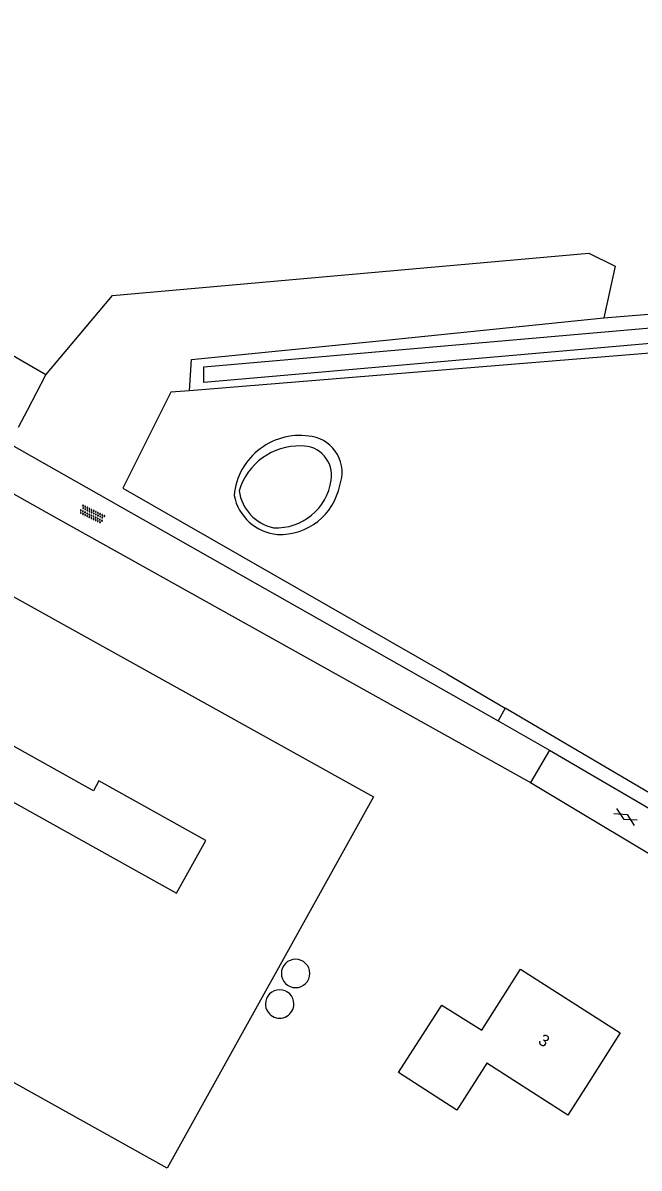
# Model space of a CAD drawing. Extents: x 133000 to 136000, y 400500 to 403500.
# Drawn here: x 134687.1 to 134739.2, y 402087.9 to 402184.6 of the extents above; entities that cross this region are included whole.
import ezdxf

# ---------------------------------------------------------------- set-up
doc = ezdxf.new("R2010")
doc.units = 0
for name, color, linetype in [('gg-afsc-draadraster', 7, 'Continuous'), ('gg-afsc-lijn draadraster', 7, 'Continuous'), ('gg-anno-huisnummerreeks BGT', 7, 'Continuous'), ('gg-bbg-bijgebouw', 7, 'Continuous'), ('gg-bbg-hoofdgebouw', 7, 'Continuous'), ('gg-bbg-opslagtank', 7, 'Continuous'), ('gg-knt-bronhoudergrens', 7, 'Continuous'), ('gg-knt-onverhard', 7, 'Continuous'), ('gg-knt-verharding', 7, 'Continuous'), ('gg-kntw-bovenkant insteek waterloop', 7, 'Continuous'), ('gg-kntw-waterlijn', 7, 'Continuous'), ('gt-grn-groengrens', 7, 'Continuous'), ('gt-symb-gesloten verharding', 7, 'Continuous'), ('gt-symb-overige verharding', 7, 'Continuous')]:
    doc.layers.add(name, color=color, linetype=linetype)

# ---------------------------------------------------------------- blocks, each defined once
blk = doc.blocks.new('gt0-GESVH1')
at = {"layer": 'gt-symb-gesloten verharding'}
for p, q in [((-0.992, -0.261), (0.008, 0.239)), ((0.008, -0.261), (-0.992, 0.239)), ((0.008, 0.239), (1.008, -0.261)), ((1.008, 0.239), (0.008, -0.261))]:
    blk.add_line(p, q, dxfattribs=at)
blk = doc.blocks.new('gt0-OVH')
at = {"layer": 'gt-symb-overige verharding'}
for points in [[(-0.972, 0.298), (-0.967, 0.308), (-0.965, 0.319), (-0.966, 0.33), (-0.971, 0.34), (-0.978, 0.348), (-0.988, 0.353), (-0.999, 0.355), (-1.01, 0.354), (-1.02, 0.349), (-1.028, 0.342), (-1.033, 0.332), (-1.035, 0.321), (-1.034, 0.31), (-1.029, 0.3), (-1.022, 0.292), (-1.012, 0.287), (-1.001, 0.285), (-0.99, 0.286), (-0.98, 0.291)], [(-0.872, 0.106), (-0.867, 0.116), (-0.865, 0.126), (-0.866, 0.137), (-0.871, 0.147), (-0.878, 0.156), (-0.888, 0.161), (-0.899, 0.163), (-0.91, 0.162), (-0.92, 0.157), (-0.928, 0.15), (-0.933, 0.14), (-0.935, 0.129), (-0.934, 0.118), (-0.929, 0.108), (-0.922, 0.1), (-0.912, 0.095), (-0.901, 0.092), (-0.89, 0.094), (-0.88, 0.098)], [(-0.772, 0.298), (-0.767, 0.308), (-0.765, 0.319), (-0.766, 0.33), (-0.771, 0.34), (-0.778, 0.348), (-0.788, 0.353), (-0.799, 0.355), (-0.81, 0.354), (-0.82, 0.349), (-0.828, 0.342), (-0.833, 0.332), (-0.835, 0.321), (-0.834, 0.31), (-0.829, 0.3), (-0.822, 0.292), (-0.812, 0.287), (-0.801, 0.285), (-0.79, 0.286), (-0.78, 0.291)], [(-0.672, 0.106), (-0.667, 0.116), (-0.665, 0.126), (-0.666, 0.137), (-0.671, 0.147), (-0.678, 0.156), (-0.688, 0.161), (-0.699, 0.163), (-0.71, 0.162), (-0.72, 0.157), (-0.728, 0.15), (-0.733, 0.14), (-0.735, 0.129), (-0.734, 0.118), (-0.729, 0.108), (-0.722, 0.1), (-0.712, 0.095), (-0.701, 0.092), (-0.69, 0.094), (-0.68, 0.098)], [(-0.572, 0.298), (-0.567, 0.308), (-0.565, 0.319), (-0.566, 0.33), (-0.571, 0.34), (-0.578, 0.348), (-0.588, 0.353), (-0.599, 0.355), (-0.61, 0.354), (-0.62, 0.349), (-0.628, 0.342), (-0.633, 0.332), (-0.635, 0.321), (-0.634, 0.31), (-0.629, 0.3), (-0.622, 0.292), (-0.612, 0.287), (-0.601, 0.285), (-0.59, 0.286), (-0.58, 0.291)], [(-0.472, 0.106), (-0.467, 0.116), (-0.465, 0.126), (-0.466, 0.137), (-0.471, 0.147), (-0.478, 0.156), (-0.488, 0.161), (-0.499, 0.163), (-0.51, 0.162), (-0.52, 0.157), (-0.528, 0.15), (-0.533, 0.14), (-0.535, 0.129), (-0.534, 0.118), (-0.529, 0.108), (-0.522, 0.1), (-0.512, 0.095), (-0.501, 0.092), (-0.49, 0.094), (-0.48, 0.098)], [(-0.372, 0.298), (-0.367, 0.308), (-0.365, 0.319), (-0.366, 0.33), (-0.371, 0.34), (-0.378, 0.348), (-0.388, 0.353), (-0.399, 0.355), (-0.41, 0.354), (-0.42, 0.349), (-0.428, 0.342), (-0.433, 0.332), (-0.435, 0.321), (-0.434, 0.31), (-0.429, 0.3), (-0.422, 0.292), (-0.412, 0.287), (-0.401, 0.285), (-0.39, 0.286), (-0.38, 0.291)], [(-0.272, 0.106), (-0.267, 0.116), (-0.265, 0.126), (-0.266, 0.137), (-0.271, 0.147), (-0.278, 0.156), (-0.288, 0.161), (-0.299, 0.163), (-0.31, 0.162), (-0.32, 0.157), (-0.328, 0.15), (-0.333, 0.14), (-0.335, 0.129), (-0.334, 0.118), (-0.329, 0.108), (-0.322, 0.1), (-0.312, 0.095), (-0.301, 0.092), (-0.29, 0.094), (-0.28, 0.098)], [(-0.172, 0.298), (-0.167, 0.308), (-0.165, 0.319), (-0.166, 0.33), (-0.171, 0.34), (-0.178, 0.348), (-0.188, 0.353), (-0.199, 0.355), (-0.21, 0.354), (-0.22, 0.349), (-0.228, 0.342), (-0.233, 0.332), (-0.235, 0.321), (-0.234, 0.31), (-0.229, 0.3), (-0.222, 0.292), (-0.212, 0.287), (-0.201, 0.285), (-0.19, 0.286), (-0.18, 0.291)], [(-0.072, 0.106), (-0.067, 0.116), (-0.065, 0.126), (-0.066, 0.137), (-0.071, 0.147), (-0.078, 0.156), (-0.088, 0.161), (-0.099, 0.163), (-0.11, 0.162), (-0.12, 0.157), (-0.128, 0.15), (-0.133, 0.14), (-0.135, 0.129), (-0.134, 0.118), (-0.129, 0.108), (-0.122, 0.1), (-0.112, 0.095), (-0.101, 0.092), (-0.09, 0.094), (-0.08, 0.098)], [(0.028, 0.298), (0.033, 0.308), (0.035, 0.319), (0.034, 0.33), (0.029, 0.34), (0.022, 0.348), (0.012, 0.353), (0.001, 0.355), (-0.01, 0.354), (-0.02, 0.349), (-0.028, 0.342), (-0.033, 0.332), (-0.035, 0.321), (-0.034, 0.31), (-0.029, 0.3), (-0.022, 0.292), (-0.012, 0.287), (-0.001, 0.285), (0.01, 0.286), (0.02, 0.291)], [(0.128, 0.106), (0.133, 0.116), (0.135, 0.126), (0.134, 0.137), (0.129, 0.147), (0.122, 0.156), (0.112, 0.161), (0.101, 0.163), (0.09, 0.162), (0.08, 0.157), (0.072, 0.15), (0.067, 0.14), (0.065, 0.129), (0.066, 0.118), (0.071, 0.108), (0.078, 0.1), (0.088, 0.095), (0.099, 0.092), (0.11, 0.094), (0.12, 0.098)], [(0.228, 0.298), (0.233, 0.308), (0.235, 0.319), (0.234, 0.33), (0.229, 0.34), (0.222, 0.348), (0.212, 0.353), (0.201, 0.355), (0.19, 0.354), (0.18, 0.349), (0.172, 0.342), (0.167, 0.332), (0.165, 0.321), (0.166, 0.31), (0.171, 0.3), (0.178, 0.292), (0.188, 0.287), (0.199, 0.285), (0.21, 0.286), (0.22, 0.291)], [(0.328, 0.106), (0.333, 0.116), (0.335, 0.126), (0.334, 0.137), (0.329, 0.147), (0.322, 0.156), (0.312, 0.161), (0.301, 0.163), (0.29, 0.162), (0.28, 0.157), (0.272, 0.15), (0.267, 0.14), (0.265, 0.129), (0.266, 0.118), (0.271, 0.108), (0.278, 0.1), (0.288, 0.095), (0.299, 0.092), (0.31, 0.094), (0.32, 0.098)], [(0.428, 0.298), (0.433, 0.308), (0.435, 0.319), (0.434, 0.33), (0.429, 0.34), (0.422, 0.348), (0.412, 0.353), (0.401, 0.355), (0.39, 0.354), (0.38, 0.349), (0.372, 0.342), (0.367, 0.332), (0.365, 0.321), (0.366, 0.31), (0.371, 0.3), (0.378, 0.292), (0.388, 0.287), (0.399, 0.285), (0.41, 0.286), (0.42, 0.291)], [(0.528, 0.106), (0.533, 0.116), (0.535, 0.126), (0.534, 0.137), (0.529, 0.147), (0.522, 0.156), (0.512, 0.161), (0.501, 0.163), (0.49, 0.162), (0.48, 0.157), (0.472, 0.15), (0.467, 0.14), (0.465, 0.129), (0.466, 0.118), (0.471, 0.108), (0.478, 0.1), (0.488, 0.095), (0.499, 0.092), (0.51, 0.094), (0.52, 0.098)], [(0.628, 0.298), (0.633, 0.308), (0.635, 0.319), (0.634, 0.33), (0.629, 0.34), (0.622, 0.348), (0.612, 0.353), (0.601, 0.355), (0.59, 0.354), (0.58, 0.349), (0.572, 0.342), (0.567, 0.332), (0.565, 0.321), (0.566, 0.31), (0.571, 0.3), (0.578, 0.292), (0.588, 0.287), (0.599, 0.285), (0.61, 0.286), (0.62, 0.291)], [(0.728, 0.106), (0.733, 0.116), (0.735, 0.126), (0.734, 0.137), (0.729, 0.147), (0.722, 0.156), (0.712, 0.161), (0.701, 0.163), (0.69, 0.162), (0.68, 0.157), (0.672, 0.15), (0.667, 0.14), (0.665, 0.129), (0.666, 0.118), (0.671, 0.108), (0.678, 0.1), (0.688, 0.095), (0.699, 0.092), (0.71, 0.094), (0.72, 0.098)], [(0.828, 0.298), (0.833, 0.308), (0.835, 0.319), (0.834, 0.33), (0.829, 0.34), (0.822, 0.348), (0.812, 0.353), (0.801, 0.355), (0.79, 0.354), (0.78, 0.349), (0.772, 0.342), (0.767, 0.332), (0.765, 0.321), (0.766, 0.31), (0.771, 0.3), (0.778, 0.292), (0.788, 0.287), (0.799, 0.285), (0.81, 0.286), (0.82, 0.291)], [(0.928, 0.106), (0.933, 0.116), (0.935, 0.126), (0.934, 0.137), (0.929, 0.147), (0.922, 0.156), (0.912, 0.161), (0.901, 0.163), (0.89, 0.162), (0.88, 0.157), (0.872, 0.15), (0.867, 0.14), (0.865, 0.129), (0.866, 0.118), (0.871, 0.108), (0.878, 0.1), (0.888, 0.095), (0.899, 0.092), (0.91, 0.094), (0.92, 0.098)], [(1.028, 0.298), (1.033, 0.308), (1.035, 0.319), (1.034, 0.33), (1.029, 0.34), (1.022, 0.348), (1.012, 0.353), (1.001, 0.355), (0.99, 0.354), (0.98, 0.349), (0.972, 0.342), (0.967, 0.332), (0.965, 0.321), (0.966, 0.31), (0.971, 0.3), (0.978, 0.292), (0.988, 0.287), (0.999, 0.285), (1.01, 0.286), (1.02, 0.291)], [(-0.972, -0.142), (-0.967, -0.132), (-0.965, -0.121), (-0.966, -0.11), (-0.971, -0.1), (-0.978, -0.092), (-0.988, -0.087), (-0.999, -0.085), (-1.01, -0.086), (-1.02, -0.091), (-1.028, -0.098), (-1.033, -0.108), (-1.035, -0.119), (-1.034, -0.13), (-1.029, -0.14), (-1.022, -0.148), (-1.012, -0.153), (-1.001, -0.155), (-0.99, -0.154), (-0.98, -0.149)], [(-0.872, -0.334), (-0.867, -0.324), (-0.865, -0.314), (-0.866, -0.303), (-0.871, -0.293), (-0.878, -0.284), (-0.888, -0.279), (-0.899, -0.277), (-0.91, -0.278), (-0.92, -0.283), (-0.928, -0.29), (-0.933, -0.3), (-0.935, -0.311), (-0.934, -0.322), (-0.929, -0.332), (-0.922, -0.34), (-0.912, -0.345), (-0.901, -0.348), (-0.89, -0.346), (-0.88, -0.342)], [(-0.772, -0.142), (-0.767, -0.132), (-0.765, -0.121), (-0.766, -0.11), (-0.771, -0.1), (-0.778, -0.092), (-0.788, -0.087), (-0.799, -0.085), (-0.81, -0.086), (-0.82, -0.091), (-0.828, -0.098), (-0.833, -0.108), (-0.835, -0.119), (-0.834, -0.13), (-0.829, -0.14), (-0.822, -0.148), (-0.812, -0.153), (-0.801, -0.155), (-0.79, -0.154), (-0.78, -0.149)], [(-0.672, -0.334), (-0.667, -0.324), (-0.665, -0.314), (-0.666, -0.303), (-0.671, -0.293), (-0.678, -0.284), (-0.688, -0.279), (-0.699, -0.277), (-0.71, -0.278), (-0.72, -0.283), (-0.728, -0.29), (-0.733, -0.3), (-0.735, -0.311), (-0.734, -0.322), (-0.729, -0.332), (-0.722, -0.34), (-0.712, -0.345), (-0.701, -0.348), (-0.69, -0.346), (-0.68, -0.342)], [(-0.572, -0.142), (-0.567, -0.132), (-0.565, -0.121), (-0.566, -0.11), (-0.571, -0.1), (-0.578, -0.092), (-0.588, -0.087), (-0.599, -0.085), (-0.61, -0.086), (-0.62, -0.091), (-0.628, -0.098), (-0.633, -0.108), (-0.635, -0.119), (-0.634, -0.13), (-0.629, -0.14), (-0.622, -0.148), (-0.612, -0.153), (-0.601, -0.155), (-0.59, -0.154), (-0.58, -0.149)], [(-0.472, -0.334), (-0.467, -0.324), (-0.465, -0.314), (-0.466, -0.303), (-0.471, -0.293), (-0.478, -0.284), (-0.488, -0.279), (-0.499, -0.277), (-0.51, -0.278), (-0.52, -0.283), (-0.528, -0.29), (-0.533, -0.3), (-0.535, -0.311), (-0.534, -0.322), (-0.529, -0.332), (-0.522, -0.34), (-0.512, -0.345), (-0.501, -0.348), (-0.49, -0.346), (-0.48, -0.342)], [(-0.372, -0.142), (-0.367, -0.132), (-0.365, -0.121), (-0.366, -0.11), (-0.371, -0.1), (-0.378, -0.092), (-0.388, -0.087), (-0.399, -0.085), (-0.41, -0.086), (-0.42, -0.091), (-0.428, -0.098), (-0.433, -0.108), (-0.435, -0.119), (-0.434, -0.13), (-0.429, -0.14), (-0.422, -0.148), (-0.412, -0.153), (-0.401, -0.155), (-0.39, -0.154), (-0.38, -0.149)], [(-0.272, -0.334), (-0.267, -0.324), (-0.265, -0.314), (-0.266, -0.303), (-0.271, -0.293), (-0.278, -0.284), (-0.288, -0.279), (-0.299, -0.277), (-0.31, -0.278), (-0.32, -0.283), (-0.328, -0.29), (-0.333, -0.3), (-0.335, -0.311), (-0.334, -0.322), (-0.329, -0.332), (-0.322, -0.34), (-0.312, -0.345), (-0.301, -0.348), (-0.29, -0.346), (-0.28, -0.342)], [(-0.172, -0.142), (-0.167, -0.132), (-0.165, -0.121), (-0.166, -0.11), (-0.171, -0.1), (-0.178, -0.092), (-0.188, -0.087), (-0.199, -0.085), (-0.21, -0.086), (-0.22, -0.091), (-0.228, -0.098), (-0.233, -0.108), (-0.235, -0.119), (-0.234, -0.13), (-0.229, -0.14), (-0.222, -0.148), (-0.212, -0.153), (-0.201, -0.155), (-0.19, -0.154), (-0.18, -0.149)], [(-0.072, -0.334), (-0.067, -0.324), (-0.065, -0.314), (-0.066, -0.303), (-0.071, -0.293), (-0.078, -0.284), (-0.088, -0.279), (-0.099, -0.277), (-0.11, -0.278), (-0.12, -0.283), (-0.128, -0.29), (-0.133, -0.3), (-0.135, -0.311), (-0.134, -0.322), (-0.129, -0.332), (-0.122, -0.34), (-0.112, -0.345), (-0.101, -0.348), (-0.09, -0.346), (-0.08, -0.342)], [(0.028, -0.142), (0.033, -0.132), (0.035, -0.121), (0.034, -0.11), (0.029, -0.1), (0.022, -0.092), (0.012, -0.087), (0.001, -0.085), (-0.01, -0.086), (-0.02, -0.091), (-0.028, -0.098), (-0.033, -0.108), (-0.035, -0.119), (-0.034, -0.13), (-0.029, -0.14), (-0.022, -0.148), (-0.012, -0.153), (-0.001, -0.155), (0.01, -0.154), (0.02, -0.149)], [(0.128, -0.334), (0.133, -0.324), (0.135, -0.314), (0.134, -0.303), (0.129, -0.293), (0.122, -0.284), (0.112, -0.279), (0.101, -0.277), (0.09, -0.278), (0.08, -0.283), (0.072, -0.29), (0.067, -0.3), (0.065, -0.311), (0.066, -0.322), (0.071, -0.332), (0.078, -0.34), (0.088, -0.345), (0.099, -0.348), (0.11, -0.346), (0.12, -0.342)], [(0.228, -0.142), (0.233, -0.132), (0.235, -0.121), (0.234, -0.11), (0.229, -0.1), (0.222, -0.092), (0.212, -0.087), (0.201, -0.085), (0.19, -0.086), (0.18, -0.091), (0.172, -0.098), (0.167, -0.108), (0.165, -0.119), (0.166, -0.13), (0.171, -0.14), (0.178, -0.148), (0.188, -0.153), (0.199, -0.155), (0.21, -0.154), (0.22, -0.149)], [(0.328, -0.334), (0.333, -0.324), (0.335, -0.314), (0.334, -0.303), (0.329, -0.293), (0.322, -0.284), (0.312, -0.279), (0.301, -0.277), (0.29, -0.278), (0.28, -0.283), (0.272, -0.29), (0.267, -0.3), (0.265, -0.311), (0.266, -0.322), (0.271, -0.332), (0.278, -0.34), (0.288, -0.345), (0.299, -0.348), (0.31, -0.346), (0.32, -0.342)], [(0.428, -0.142), (0.433, -0.132), (0.435, -0.121), (0.434, -0.11), (0.429, -0.1), (0.422, -0.092), (0.412, -0.087), (0.401, -0.085), (0.39, -0.086), (0.38, -0.091), (0.372, -0.098), (0.367, -0.108), (0.365, -0.119), (0.366, -0.13), (0.371, -0.14), (0.378, -0.148), (0.388, -0.153), (0.399, -0.155), (0.41, -0.154), (0.42, -0.149)], [(0.528, -0.334), (0.533, -0.324), (0.535, -0.314), (0.534, -0.303), (0.529, -0.293), (0.522, -0.284), (0.512, -0.279), (0.501, -0.277), (0.49, -0.278), (0.48, -0.283), (0.472, -0.29), (0.467, -0.3), (0.465, -0.311), (0.466, -0.322), (0.471, -0.332), (0.478, -0.34), (0.488, -0.345), (0.499, -0.348), (0.51, -0.346), (0.52, -0.342)], [(0.628, -0.142), (0.633, -0.132), (0.635, -0.121), (0.634, -0.11), (0.629, -0.1), (0.622, -0.092), (0.612, -0.087), (0.601, -0.085), (0.59, -0.086), (0.58, -0.091), (0.572, -0.098), (0.567, -0.108), (0.565, -0.119), (0.566, -0.13), (0.571, -0.14), (0.578, -0.148), (0.588, -0.153), (0.599, -0.155), (0.61, -0.154), (0.62, -0.149)], [(0.728, -0.334), (0.733, -0.324), (0.735, -0.314), (0.734, -0.303), (0.729, -0.293), (0.722, -0.284), (0.712, -0.279), (0.701, -0.277), (0.69, -0.278), (0.68, -0.283), (0.672, -0.29), (0.667, -0.3), (0.665, -0.311), (0.666, -0.322), (0.671, -0.332), (0.678, -0.34), (0.688, -0.345), (0.699, -0.348), (0.71, -0.346), (0.72, -0.342)], [(0.828, -0.142), (0.833, -0.132), (0.835, -0.121), (0.834, -0.11), (0.829, -0.1), (0.822, -0.092), (0.812, -0.087), (0.801, -0.085), (0.79, -0.086), (0.78, -0.091), (0.772, -0.098), (0.767, -0.108), (0.765, -0.119), (0.766, -0.13), (0.771, -0.14), (0.778, -0.148), (0.788, -0.153), (0.799, -0.155), (0.81, -0.154), (0.82, -0.149)], [(0.928, -0.334), (0.933, -0.324), (0.935, -0.314), (0.934, -0.303), (0.929, -0.293), (0.922, -0.284), (0.912, -0.279), (0.901, -0.277), (0.89, -0.278), (0.88, -0.283), (0.872, -0.29), (0.867, -0.3), (0.865, -0.311), (0.866, -0.322), (0.871, -0.332), (0.878, -0.34), (0.888, -0.345), (0.899, -0.348), (0.91, -0.346), (0.92, -0.342)], [(1.028, -0.142), (1.033, -0.132), (1.035, -0.121), (1.034, -0.11), (1.029, -0.1), (1.022, -0.092), (1.012, -0.087), (1.001, -0.085), (0.99, -0.086), (0.98, -0.091), (0.972, -0.098), (0.967, -0.108), (0.965, -0.119), (0.966, -0.13), (0.971, -0.14), (0.978, -0.148), (0.988, -0.153), (0.999, -0.155), (1.01, -0.154), (1.02, -0.149)]]:
    blk.add_lwpolyline(points, close=True, dxfattribs=at)

msp = doc.modelspace()

# ---------------------------------------------------------------- linework, layer by layer
at = {"layer": 'gg-afsc-draadraster'}
for p, q in [((134737.15, 402164.068), (134736.179, 402159.699)), ((134689.031, 402154.89), (134694.679, 402161.595))]:
    msp.add_line(p, q, dxfattribs=at)
msp.add_lwpolyline([(134694.679, 402161.595), (134734.922, 402165.152), (134737.15, 402164.068)], dxfattribs=at)
at = {"layer": 'gg-afsc-lijn draadraster'}
for p, q in [((134737.15, 402164.068), (134736.179, 402159.699)), ((134689.031, 402154.89), (134694.679, 402161.595))]:
    msp.add_line(p, q, dxfattribs=at)
msp.add_lwpolyline([(134694.679, 402161.595), (134734.922, 402165.152), (134737.15, 402164.068)], dxfattribs=at)
at = {"layer": 'gg-bbg-bijgebouw'}
for points in [[(134685.791, 402136.46), (134716.711, 402119.24), (134699.292, 402087.9), (134672.722, 402102.71), (134676.372, 402109.255)], [(134676.372, 402109.255), (134682.781, 402120.75), (134700.081, 402111.11), (134702.561, 402115.57), (134693.53, 402120.6), (134693.071, 402119.76), (134680.41, 402126.811), (134685.791, 402136.46)]]:
    msp.add_lwpolyline(points, dxfattribs=at)
at = {"layer": 'gg-bbg-hoofdgebouw'}
for points in [[(134719.791, 402097.451), (134722.49, 402101.66), (134725.872, 402099.54), (134729.15, 402104.7), (134737.571, 402099.311), (134734.871, 402095.1)], [(134734.871, 402095.1), (134733.129, 402092.383), (134726.31, 402096.755), (134723.773, 402092.798), (134718.837, 402095.962), (134719.791, 402097.451)]]:
    msp.add_lwpolyline(points, dxfattribs=at)
at = {"layer": 'gg-bbg-opslagtank'}
for centre, start, end in [((134710.141, 402104.337), 0, 180), ((134710.141, 402104.337), 180, 0), ((134708.796, 402101.76), 0.09552, 180.04772), ((134708.796, 402101.76), 180.04772, 0.09552)]:
    msp.add_arc(centre, 1.2, start, end, dxfattribs=at)
at = {"layer": 'gg-knt-bronhoudergrens'}
msp.add_line((134740.491, 402119.315), (134727.854, 402126.725), dxfattribs=at)
msp.add_lwpolyline([(134701.179, 402153.537), (134699.593, 402153.407), (134695.55, 402145.321), (134722.905, 402129.627), (134727.854, 402126.725)], dxfattribs=at)
at = {"layer": 'gg-knt-onverhard'}
for p, q in [((134685.945, 402149.073), (134727.248, 402125.657)), ((134684.397, 402145.889), (134689.981, 402142.774)), ((134689.981, 402142.774), (134729.971, 402120.47)), ((134727.248, 402125.657), (134731.582, 402123.2))]:
    msp.add_line(p, q, dxfattribs=at)
at = {"layer": 'gg-knt-verharding'}
for q in [(134729.971, 402120.47), (134748.808, 402113.136)]:
    msp.add_line((134731.582, 402123.2), q, dxfattribs=at)
msp.add_lwpolyline([(134729.971, 402120.47), (134743.84, 402112.15), (134745.946, 402110.758), (134748.11, 402109.458), (134750.328, 402108.252), (134752.596, 402107.142), (134754.926, 402106.172)], dxfattribs=at)
at = {"layer": 'gg-kntw-bovenkant insteek waterloop'}
for p, q in [((134689.031, 402154.89), (134637.561, 402184.6)), ((134736.179, 402159.699), (134809.009, 402165.492)), ((134687.484, 402151.911), (134689.031, 402154.89)), ((134686.731, 402150.46), (134687.484, 402151.911))]:
    msp.add_line(p, q, dxfattribs=at)
for points in [[(134809.009, 402162.714), (134739.401, 402156.664), (134701.179, 402153.537)], [(134701.179, 402153.537), (134701.345, 402156.181), (134717.758, 402157.809), (134736.179, 402159.699)]]:
    msp.add_lwpolyline(points, dxfattribs=at)
for centre, radius, start, end in [((134710.508, 402144.179), 5.585, 79.25241, 174.58175), ((134711.001, 402146.645), 3.07, 339.09548, 79.6993), ((134708.822, 402146.543), 5.143, 267.72288, 348.86381), ((134708.994, 402145.513), 4.126, 191.27474, 264.76809)]:
    msp.add_arc(centre, radius, start, end, dxfattribs=at)
at = {"layer": 'gg-kntw-waterlijn'}
msp.add_lwpolyline([(134702.399, 402155.56), (134781.724, 402162.474), (134806.977, 402164.517), (134806.977, 402163.388), (134736.586, 402157.227), (134702.397, 402154.243), (134702.399, 402155.56)], dxfattribs=at)
for centre, radius, start, end in [((134710.439, 402143.605), 5.275, 88.16465, 163.70234), ((134710.704, 402146.402), 2.476, 350.55304, 92.22585), ((134708.504, 402146.65), 4.689, 267.20476, 351.98869), ((134709.078, 402145.619), 3.741, 188.21339, 257.59935)]:
    msp.add_arc(centre, radius, start, end, dxfattribs=at)
at = {"layer": 'gt-grn-groengrens'}
msp.add_line((134727.854, 402126.725), (134727.248, 402125.657), dxfattribs=at)

# ---------------------------------------------------------------- block references
at = {"layer": 'gt-symb-gesloten verharding', "rotation": -30.25643716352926}
msp.add_blockref('gt0-GESVH1', (134738.016, 402117.568), dxfattribs=at)
at = {"layer": 'gt-symb-overige verharding', "rotation": -26.027198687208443}
msp.add_blockref('gt0-OVH', (134692.947, 402143.111), dxfattribs=at)

# ---------------------------------------------------------------- texts
at = {"layer": 'gg-anno-huisnummerreeks BGT'}
msp.add_text('3', height=1, rotation=327.4, dxfattribs=at).set_placement((134730.557, 402098.456))

doc.saveas('drawing.dxf')
